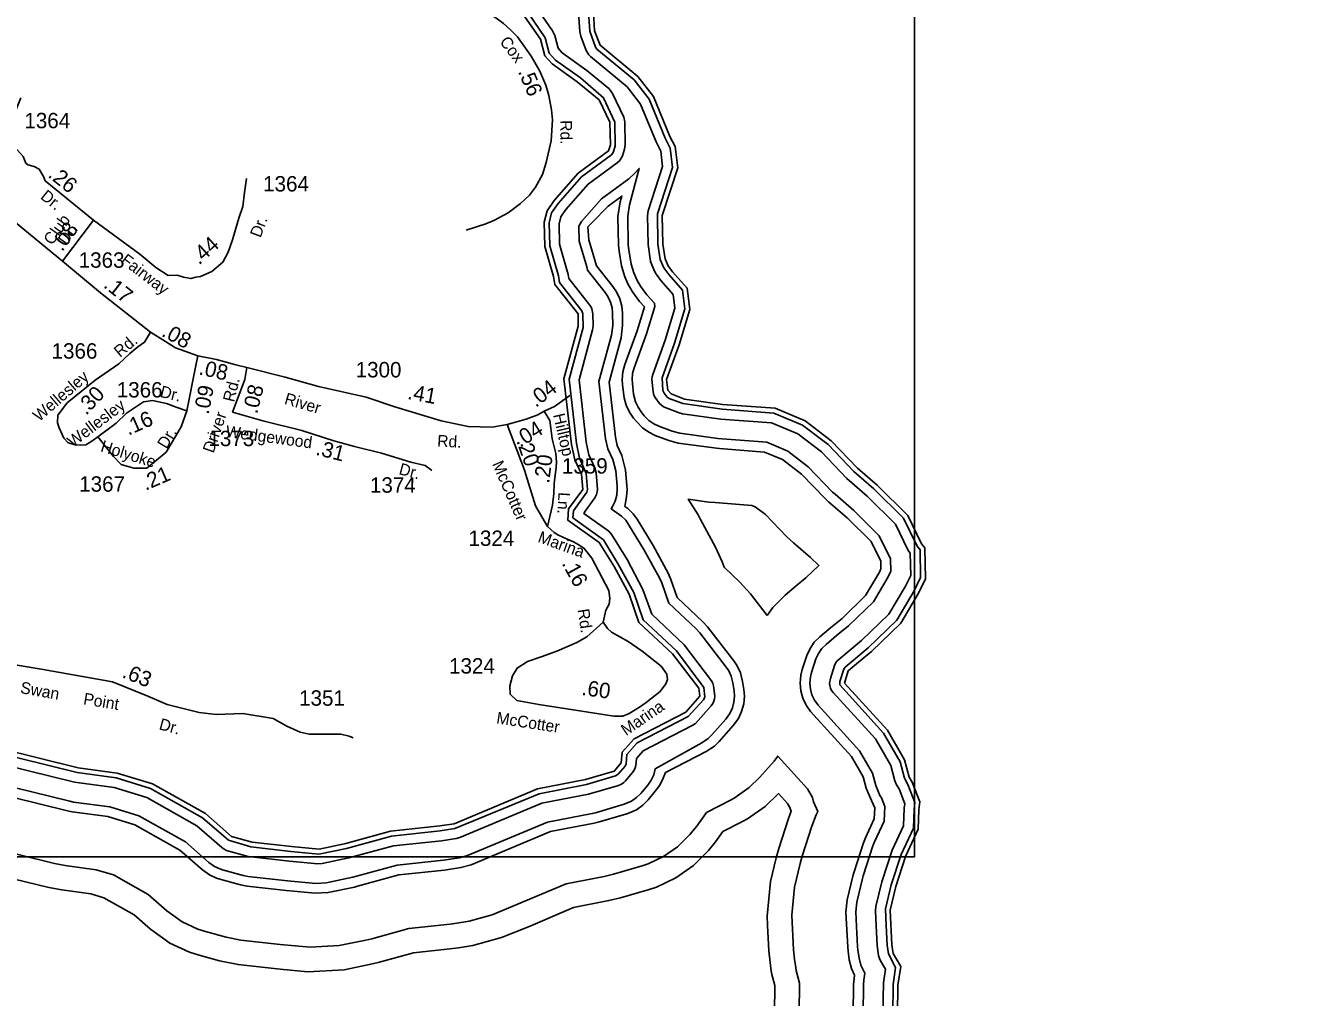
# Model space of a CAD drawing. Extents: x 2532689 to 2764727, y 536648 to 732970.
# Drawn here: x 2602829 to 2613131, y 635210 to 643101 of the extents above; entities that cross this region are included whole.
import ezdxf

# ---------------------------------------------------------------- set-up
doc = ezdxf.new("R2010")
doc.units = 0
for name, color, linetype in [('Exist Hydrographic Buffer Line', 7, 'Continuous'), ('Exist Hydrographic River Shore', 7, 'Continuous'), ('Exist Road Secondary Mileage Hundredths English Label', 7, 'Continuous'), ('Exist Road Secondary Type 51 Attributed', 7, 'Continuous'), ('Exist Road Secondary Type 51 Label', 7, 'Continuous'), ('Exist Road Secondary Type 51 Number Label', 7, 'Continuous'), ('Map Preparation Inset Cut Line', 7, 'Continuous')]:
    doc.layers.add(name, color=color, linetype=linetype)

msp = doc.modelspace()

# ---------------------------------------------------------------- linework, layer by layer
at = {"layer": 'Exist Hydrographic Buffer Line'}
for points in [[(2606910, 643202), (2607049, 642999)], [(2607643, 636932), (2607669, 636943), (2607687, 636955), (2607701, 636970), (2607758, 637038), (2607770, 637055), (2607779, 637074), (2607785, 637094), (2607789, 637151), (2607845, 637213), (2608246, 637420), (2608268, 637435), (2608395, 637577), (2608409, 637596), (2608418, 637615), (2608423, 637636), (2608425, 637656), (2608414, 637740), (2608408, 637763), (2608399, 637782), (2608176, 638072), (2607913, 638321), (2607842, 638523), (2607713, 638766), (2607590, 638967), (2607565, 638996), (2607361, 639140), (2607374, 639158), (2607451, 639265), (2607466, 639294), (2607471, 639314), (2607473, 639335), (2607462, 639470), (2607451, 639509), (2607404, 639614), (2607381, 639719), (2607323, 640223), (2607433, 640629), (2607437, 640663), (2607435, 640761), (2607428, 640800), (2607419, 640819), (2607241, 641046), (2607236, 641079), (2607165, 641324), (2607161, 641489), (2607175, 641546), (2607216, 641606), (2607398, 641812), (2607633, 641985), (2607654, 642005), (2607666, 642022), (2607675, 642041), (2607692, 642095), (2607698, 642134), (2607694, 642318), (2607687, 642356), (2607595, 642548), (2607579, 642573), (2607564, 642588), (2607386, 642735), (2607187, 642879), (2607154, 642915), (2607126, 643020), (2607109, 643057), (2607000, 643213)], [(2607320, 643206), (2607330, 643048), (2607338, 643013), (2607382, 642897), (2607402, 642862), (2607417, 642847), (2607714, 642601), (2607823, 642462), (2607949, 642155), (2607987, 642081), (2608002, 641956), (2607884, 641595), (2607878, 641555), (2607883, 641322), (2607904, 641188), (2607913, 641158), (2607939, 641100), (2607951, 641079), (2607986, 641031), (2608088, 640917), (2608101, 640806), (2608023, 640547), (2607921, 640267), (2607916, 640247), (2607914, 640226), (2607925, 640127)], [(2609958, 639100), (2609717, 639340), (2609555, 639480), (2609344, 639699), (2609138, 639856), (2608905, 639953), (2608484, 639985), (2608165, 640031), (2608056, 640072), (2608039, 640084), (2608013, 640116), (2608004, 640137), (2607997, 640240), (2608099, 640522), (2608182, 640799), (2608164, 640951), (2608051, 641078), (2608012, 641133), (2607983, 641201), (2607963, 641324), (2607960, 641570), (2608083, 641948), (2608064, 642105), (2608023, 642185), (2607893, 642503), (2607771, 642658), (2607468, 642909), (2607457, 642925), (2607410, 643053), (2607400, 643208)], [(2607049, 642999), (2607082, 642875), (2607133, 642819), (2607335, 642674), (2607523, 642513), (2607614, 642316), (2607616, 642120), (2607600, 642068), (2607586, 642050), (2607343, 641871), (2607153, 641655), (2607101, 641579), (2607081, 641498), (2607085, 641312), (2607157, 641068), (2607164, 641013), (2607346, 640783), (2607355, 640759), (2607356, 640650), (2607242, 640229), (2607302, 639706), (2607327, 639588), (2607382, 639463), (2607393, 639335), (2607386, 639312), (2607278, 639162), (2607274, 639104), (2607521, 638925), (2607642, 638728), (2607767, 638497), (2607844, 638276), (2608113, 638023), (2608335, 637728), (2608345, 637650), (2608335, 637630), (2608209, 637492), (2607795, 637278), (2607711, 637184), (2607706, 637108), (2607697, 637089), (2607640, 637022), (2607620, 637009), (2607385, 636939), (2606999, 636865), (2606315, 636581), (2606197, 636563), (2605802, 636521), (2605437, 636421), (2605210, 636375), (2604984, 636396), (2604660, 636433), (2604477, 636488), (2604268, 636670), (2603845, 636908), (2603567, 636993), (2603249, 637036), (2602294, 637271)], [(2609575, 635788), (2609570, 635906), (2609577, 635985), (2609623, 636177), (2609629, 636199), (2609708, 636442), (2609721, 636473), (2609799, 636642), (2609804, 636762), (2609777, 636832), (2609765, 636851), (2609731, 636930), (2609705, 637032), (2609600, 637214), (2609263, 637583), (2609235, 637623), (2609214, 637667), (2609201, 637714), (2609197, 637763), (2609201, 637812), (2609211, 637849), (2609246, 637959), (2609267, 638003), (2609295, 638043), (2609329, 638077), (2609414, 638149), (2609511, 638228), (2609712, 638423), (2609832, 638625), (2609854, 638671), (2609852, 638770), (2609760, 638958), (2609554, 639164), (2609401, 639295), (2609381, 639313), (2609183, 639519), (2609017, 639646), (2608848, 639717), (2608451, 639747), (2608140, 639791), (2608079, 639806), (2607971, 639848), (2607930, 639867), (2607890, 639895), (2607853, 639932), (2607827, 639964), (2607802, 640001), (2607781, 640045), (2607766, 640108), (2607756, 640193), (2607754, 640226), (2607758, 640275), (2607771, 640322), (2607871, 640598), (2607938, 640820), (2607935, 640847), (2607874, 640915), (2607857, 640936), (2607822, 640984), (2607793, 641035), (2607767, 641093), (2607746, 641163), (2607727, 641280), (2607723, 641319), (2607718, 641552), (2607732, 641645), (2607812, 641940), (2607777, 641902), (2607728, 641856), (2607506, 641693), (2607343, 641508), (2607322, 641471), (2607324, 641349), (2607386, 641142), (2607392, 641113), (2607535, 640932), (2607558, 640899), (2607578, 640854), (2607591, 640807), (2607595, 640764), (2607597, 640666), (2607587, 640587)], [(2609549, 635076), (2609552, 635316), (2609556, 635363), (2609560, 635392), (2609535, 635446), (2609517, 635517), (2609507, 635586), (2609504, 635620), (2609490, 635902), (2609499, 636003), (2609545, 636196), (2609553, 636223), (2609632, 636466), (2609648, 636507), (2609720, 636661), (2609723, 636749), (2609697, 636809), (2609654, 636910), (2609630, 637002), (2609535, 637166), (2609201, 637532), (2609166, 637583), (2609139, 637640), (2609123, 637701), (2609117, 637763), (2609123, 637826), (2609135, 637873), (2609171, 637986), (2609198, 638043), (2609233, 638094), (2609278, 638138), (2609364, 638211), (2609458, 638288), (2609649, 638473), (2609761, 638663), (2609774, 638689), (2609772, 638751), (2609694, 638911), (2609500, 639105), (2609349, 639234), (2609324, 639258), (2609130, 639459), (2608976, 639576), (2608829, 639638), (2608462, 639666), (2608439, 639668), (2608129, 639711), (2608051, 639731), (2607942, 639773), (2607890, 639798), (2607839, 639834), (2607791, 639882), (2607765, 639913), (2607732, 639961), (2607706, 640018), (2607690, 640079), (2607687, 640099), (2607677, 640184), (2607674, 640226), (2607680, 640289), (2607696, 640349), (2607795, 640623), (2607854, 640817), (2607815, 640861), (2607793, 640889), (2607758, 640937), (2607720, 641002), (2607694, 641060), (2607667, 641150), (2607648, 641267), (2607643, 641317), (2607638, 641550), (2607656, 641669), (2607671, 641715), (2607561, 641634), (2607426, 641497), (2607394, 641465), (2607404, 641361), (2607466, 641148), (2607597, 640982)], [(2607597, 640982), (2607627, 640939), (2607653, 640882), (2607670, 640821), (2607675, 640766), (2607677, 640667), (2607665, 640566), (2607567, 640204), (2607618, 639758), (2607633, 639690), (2607670, 639609), (2607701, 639491), (2607712, 639367), (2607713, 639335), (2607708, 639273), (2607695, 639197), (2607719, 639180), (2607763, 639135), (2607794, 639092), (2607924, 638880), (2608046, 638655), (2608069, 638602), (2608120, 638456), (2608328, 638261), (2608366, 638219), (2608580, 637942), (2608607, 637902), (2608633, 637845), (2608651, 637776), (2608661, 637711), (2608665, 637656), (2608660, 637594), (2608643, 637533), (2608617, 637476), (2608575, 637418), (2608461, 637289), (2608423, 637251), (2608356, 637207), (2608025, 637036), (2608005, 636992), (2607978, 636935), (2607942, 636884), (2607885, 636816), (2607841, 636771), (2607789, 636735), (2607732, 636709), (2607711, 636702), (2607479, 636633), (2607445, 636625), (2607092, 636557), (2606448, 636288), (2606364, 636265), (2606231, 636245), (2605861, 636205), (2605524, 636113), (2605502, 636107), (2605286, 636063), (2605181, 636057), (2604947, 636078), (2604629, 636114), (2604575, 636125), (2604408, 636171), (2604380, 636179), (2604323, 636206), (2604266, 636247), (2604082, 636407), (2603719, 636612), (2603498, 636679), (2603210, 636718), (2603172, 636725), (2602282, 636944)], [(2607587, 640587), (2607485, 640210), (2607539, 639745), (2607557, 639665), (2607597, 639576), (2607621, 639484), (2607632, 639360), (2607633, 639335), (2607629, 639287), (2607616, 639239), (2607596, 639195), (2607585, 639178), (2607649, 639132), (2607667, 639118), (2607702, 639084), (2607726, 639050), (2607853, 638842), (2607975, 638617), (2607994, 638576), (2608051, 638411), (2608273, 638203), (2608303, 638170), (2608517, 637893), (2608538, 637862), (2608558, 637818), (2608572, 637764), (2608582, 637699), (2608585, 637656), (2608581, 637608), (2608568, 637561), (2608548, 637516), (2608515, 637471), (2608401, 637342), (2608371, 637313), (2608320, 637278), (2607942, 637067), (2607929, 637019), (2607909, 636975), (2607881, 636935), (2607824, 636867), (2607789, 636833), (2607749, 636805), (2607689, 636779), (2607456, 636710), (2607430, 636704), (2607068, 636634), (2606417, 636362), (2606352, 636344), (2606223, 636324), (2605846, 636284), (2605486, 636186), (2605270, 636141), (2605188, 636136), (2604956, 636157), (2604638, 636194), (2604596, 636202), (2604429, 636248), (2604407, 636255), (2604363, 636275), (2604319, 636307), (2604129, 636473), (2603750, 636686), (2603515, 636757), (2603220, 636797), (2603191, 636803), (2602285, 637026)], [(2607925, 640127), (2607931, 640100), (2607940, 640081), (2607977, 640033), (2607993, 640017), (2608010, 640005), (2608136, 639956), (2608163, 639949), (2608473, 639906), (2608886, 639874), (2609098, 639786), (2609290, 639639), (2609497, 639424), (2609663, 639281), (2609892, 639053), (2609996, 638839), (2610011, 638816), (2610015, 638637), (2609973, 638550), (2609839, 638323), (2609617, 638108), (2609516, 638025), (2609432, 637955), (2609417, 637940), (2609405, 637923), (2609396, 637904), (2609363, 637800), (2609357, 637763), (2609359, 637742), (2609364, 637722), (2609373, 637703), (2609385, 637686), (2609730, 637309), (2609854, 637093), (2609886, 636970), (2609900, 636936), (2609921, 636904), (2609967, 636783), (2609963, 636746), (2609958, 636604), (2609866, 636406), (2609781, 636149), (2609733, 635948), (2609729, 635914), (2609736, 635791)], [(2608850, 638312), (2608714, 638488), (2608628, 638582), (2608500, 638703), (2608485, 638747), (2608432, 638865), (2608310, 639090), (2608289, 639127), (2608210, 639256), (2608378, 639232), (2608429, 639227), (2608726, 639205), (2608754, 639192), (2608836, 639130), (2609007, 638952), (2609063, 638900), (2609201, 638782), (2609270, 638718), (2609165, 638617), (2609086, 638552), (2608995, 638475), (2608897, 638377), (2608850, 638312)], [(2609816, 635795), (2609810, 635929), (2609857, 636124), (2609938, 636372), (2610038, 636585), (2610043, 636738), (2610049, 636794), (2609992, 636940), (2609964, 636990), (2609929, 637124), (2609795, 637356), (2609440, 637749), (2609439, 637775), (2609472, 637876), (2609484, 637893), (2609566, 637963), (2609671, 638048), (2609903, 638273), (2610044, 638512), (2610095, 638619), (2610091, 638845), (2610068, 638874), (2609958, 639100)], [(2602291, 637189), (2603229, 636958), (2603549, 636914), (2603814, 636834), (2604222, 636604), (2604424, 636427), (2604443, 636414), (2604462, 636405), (2604638, 636356), (2604974, 636316), (2605202, 636296), (2605238, 636298), (2605454, 636343), (2605816, 636442), (2606206, 636483), (2606327, 636502), (2606356, 636510), (2607022, 636788), (2607400, 636861), (2607643, 636932)], [(2602266, 636495), (2603067, 636298), (2603151, 636282), (2603404, 636248), (2603545, 636205), (2603827, 636046), (2603977, 635915), (2604103, 635825), (2604230, 635766), (2604291, 635746), (2604458, 635700), (2604579, 635677), (2604897, 635641), (2605141, 635618), (2605376, 635632), (2605592, 635677), (2605641, 635688), (2605943, 635771), (2606278, 635807), (2606315, 635812), (2606431, 635830), (2606618, 635882), (2607219, 636134), (2607528, 636193), (2607603, 636211), (2607835, 636280), (2607883, 636295), (2608009, 636354), (2608123, 636434), (2608222, 636533), (2608279, 636601), (2608357, 636712), (2608558, 636816), (2608591, 636834), (2608705, 636914), (2608792, 636998), (2608906, 637128), (2608936, 637170), (2609178, 636905), (2609219, 636834), (2609227, 636800), (2609262, 636720), (2609249, 636693), (2609214, 636602), (2609135, 636359), (2609117, 636298)], [(2606914, 635784), (2607277, 635941), (2607566, 635997), (2607660, 636020), (2607892, 636088), (2607951, 636107), (2608109, 636181), (2608252, 636281), (2608375, 636404), (2608432, 636473), (2608491, 636557), (2608650, 636638), (2608691, 636661), (2608834, 636761), (2608942, 636866), (2609016, 636786), (2609032, 636757), (2609046, 636723), (2609023, 636664), (2608944, 636421), (2608923, 636345), (2608877, 636152), (2608851, 635870), (2608854, 635795)], [(2602249, 636289), (2603019, 636104), (2603124, 636084), (2603361, 636052), (2603466, 636020), (2603711, 635882), (2603845, 635764), (2604003, 635652), (2604161, 635578), (2604239, 635553), (2604406, 635508), (2604556, 635478), (2604874, 635442), (2604898, 635440), (2605123, 635419), (2605417, 635436), (2605633, 635481), (2605694, 635496), (2605980, 635574), (2606299, 635608), (2606345, 635614), (2606461, 635632), (2606695, 635698), (2606914, 635784)], [(2609117, 636298), (2609071, 636106), (2609050, 635880), (2609064, 635598), (2609072, 635522)], [(2608854, 635795), (2608865, 635588), (2608874, 635494), (2608884, 635425), (2608889, 635396), (2608912, 635307), (2608909, 635084)], [(2610230, 634303), (2610191, 634327), (2610030, 634442), (2609993, 634473), (2609865, 634602), (2609848, 634621), (2609746, 634745), (2609698, 634829), (2609646, 634978), (2609633, 635023), (2609629, 635075), (2609632, 635315), (2609635, 635352), (2609643, 635408), (2609631, 635430), (2609610, 635474), (2609596, 635529), (2609586, 635597), (2609583, 635624), (2609575, 635788)], [(2609736, 635791), (2609744, 635632), (2609754, 635552), (2609761, 635528), (2609769, 635509), (2609810, 635440), (2609794, 635329), (2609789, 635073), (2609791, 635051), (2609796, 635032), (2609849, 634883), (2609869, 634847), (2609972, 634723), (2610107, 634585), (2610123, 634572), (2610283, 634457), (2610898, 634153), (2611106, 634079), (2611738, 633775), (2611965, 633604), (2612368, 633384), (2612394, 633373), (2613157, 633165), (2613188, 633160)], [(2613599, 633293), (2613575, 633282), (2613178, 633242), (2612406, 633454), (2612013, 633668), (2611780, 633843), (2611137, 634153), (2610934, 634224), (2610330, 634522), (2610164, 634641), (2610033, 634774), (2609925, 634909), (2609869, 635072), (2609873, 635317), (2609893, 635455), (2609834, 635564), (2609823, 635636), (2609816, 635795)], [(2609109, 635082), (2609113, 635328), (2609086, 635430), (2609082, 635454), (2609072, 635522)]]:
    msp.add_lwpolyline(points, dxfattribs=at)
at = {"layer": 'Exist Hydrographic River Shore'}
for points in [[(2608305, 637656), (2608295, 637722), (2608081, 637999), (2607809, 638254), (2607729, 638484), (2607607, 638708), (2607487, 638904), (2607233, 639084), (2607239, 639176), (2607353, 639335), (2607342, 639459), (2607289, 639575), (2607262, 639699), (2607201, 640232), (2607317, 640660), (2607315, 640759), (2607126, 640997), (2607117, 641062), (2607045, 641306), (2607041, 641503), (2607064, 641595), (2607121, 641680), (2607316, 641901), (2607562, 642082), (2607578, 642132), (2607574, 642315), (2607487, 642496), (2607309, 642643), (2607106, 642789), (2607046, 642855), (2607010, 642989), (2606865, 643197)], [(2609477, 637763), (2609509, 637863), (2609591, 637932), (2609697, 638018), (2609934, 638248), (2610079, 638493), (2610135, 638610), (2610130, 638860), (2610104, 638892), (2609991, 639123), (2609744, 639369), (2609583, 639507), (2609370, 639729), (2609158, 639891), (2608914, 639993), (2608489, 640025), (2608179, 640068), (2608070, 640109), (2608044, 640141), (2608034, 640226), (2608137, 640509), (2608223, 640795), (2608202, 640968), (2608083, 641101), (2608048, 641149), (2608022, 641207), (2608003, 641325), (2607998, 641558), (2608124, 641944), (2608103, 642117), (2608060, 642200), (2607928, 642523), (2607800, 642686), (2607494, 642939), (2607450, 643056), (2607440, 643209)], [(2609909, 635072), (2609912, 635312), (2609934, 635463), (2609873, 635569), (2609863, 635638), (2609849, 635920), (2609895, 636112), (2609974, 636355), (2610077, 636576), (2610082, 636734), (2610089, 636800), (2610028, 636958), (2610002, 637000), (2609966, 637139), (2609827, 637380), (2609477, 637763)], [(2608305, 637656), (2608191, 637527), (2607770, 637310), (2607672, 637201), (2607666, 637115), (2607609, 637047), (2607377, 636979), (2606987, 636904), (2606309, 636620), (2606193, 636603), (2605794, 636560), (2605429, 636460), (2605213, 636415), (2604988, 636436), (2604670, 636472), (2604503, 636518), (2604291, 636703), (2603861, 636945), (2603575, 637032), (2603258, 637075), (2602295, 637312)]]:
    msp.add_lwpolyline(points, dxfattribs=at)
at = {"layer": 'Exist Road Secondary Type 51 Attributed'}
msp.add_line((2603130, 641186), (2603381, 641520), dxfattribs=at)
for points in [[(2606417, 643273), (2606569, 643213), (2606591, 643195), (2606649, 643161), (2606711, 643116), (2606766, 643066), (2606824, 643007), (2606935, 642851), (2607004, 642729), (2607055, 642617), (2607079, 642533), (2607101, 642416), (2607109, 642333), (2607097, 642165), (2607057, 641988), (2607026, 641891), (2606970, 641788), (2606921, 641723), (2606848, 641655), (2606749, 641579), (2606638, 641521), (2606567, 641491), (2606407, 641440)], [(2602792, 642514), (2602754, 642417), (2602718, 642304), (2602712, 642229), (2602721, 642171), (2602741, 642116), (2602812, 642038), (2602832, 641983), (2602848, 641970), (2602901, 641956), (2602942, 641934), (2602969, 641889), (2602977, 641874), (2602990, 641840), (2603381, 641520)], [(2603381, 641520), (2603759, 641243), (2603889, 641135), (2603988, 641070), (2604060, 641074), (2604112, 641057), (2604171, 641046), (2604214, 641058), (2604250, 641062), (2604342, 641103), (2604431, 641180), (2604474, 641260), (2604510, 641359), (2604536, 641445), (2604563, 641537), (2604594, 641631), (2604608, 641745), (2604624, 641858)], [(2602442, 641746), (2602470, 641729), (2603130, 641186)], [(2603130, 641186), (2603439, 640931), (2603844, 640611)], [(2603417, 639762), (2603360, 639722), (2603319, 639697), (2603278, 639694), (2603234, 639697), (2603177, 639713), (2603142, 639750), (2603103, 639834), (2603090, 639876), (2603092, 639938), (2603169, 640037), (2603396, 640220), (2603589, 640354), (2603678, 640437), (2603741, 640491), (2603797, 640530), (2603844, 640611)], [(2603844, 640611), (2603966, 640536), (2604049, 640483), (2604123, 640457), (2604230, 640419)], [(2604230, 640419), (2604213, 640339), (2604141, 639971)], [(2604230, 640419), (2604380, 640390), (2604538, 640346), (2604626, 640323)], [(2604626, 640323), (2604610, 640227), (2604511, 639962)], [(2604626, 640323), (2604939, 640246), (2605209, 640170), (2605596, 640083), (2605828, 640004), (2606203, 639890), (2606423, 639844), (2606619, 639840), (2606741, 639861)], [(2607040, 639969), (2607124, 640007), (2607249, 640098)], [(2604141, 639971), (2604053, 640001), (2603974, 640031), (2603861, 640056), (2603787, 640045), (2603649, 639953), (2603565, 639873), (2603417, 639762)], [(2604141, 639971), (2604094, 639842), (2603972, 639636), (2603815, 639507)], [(2606741, 639861), (2606894, 639905), (2606990, 639940), (2607040, 639969)], [(2607040, 639969), (2607086, 639893), (2607094, 639831), (2607106, 639745), (2607134, 639627), (2607141, 639557), (2607137, 639514), (2607120, 639382), (2607118, 639301), (2607108, 639206), (2607066, 639033)], [(2604511, 639962), (2604757, 639890), (2605074, 639813), (2605334, 639729), (2605502, 639683), (2605721, 639629), (2605958, 639557), (2606075, 639528), (2606115, 639499), (2606128, 639487)], [(2603815, 639507), (2603709, 639506), (2603606, 639538), (2603545, 639601), (2603417, 639762)], [(2606741, 639861), (2606880, 639490), (2606970, 639201), (2607020, 639111), (2607066, 639033)], [(2607066, 639033), (2607120, 638986), (2607150, 638965), (2607197, 638945), (2607278, 638910), (2607322, 638885), (2607366, 638855), (2607426, 638776), (2607564, 638514), (2607573, 638451), (2607568, 638403), (2607541, 638354), (2607518, 638256)], [(2607518, 638256), (2607387, 638139), (2607304, 638093), (2607142, 638021), (2607017, 637976), (2606905, 637939), (2606822, 637885), (2606782, 637821), (2606761, 637739), (2606763, 637672), (2606819, 637621), (2606998, 637589), (2607312, 637541)], [(2607312, 637541), (2607606, 637493), (2607680, 637493), (2607731, 637517), (2607814, 637568), (2607867, 637605), (2607981, 637693), (2608029, 637757), (2608040, 637792), (2608037, 637835), (2607989, 637899), (2607835, 638021), (2607723, 638101), (2607654, 638139), (2607587, 638176), (2607555, 638205), (2607518, 638256)], [(2602282, 638084), (2602357, 638006), (2602465, 637956), (2602974, 637874), (2603536, 637774), (2603824, 637656), (2603981, 637588), (2604239, 637524), (2604378, 637508), (2604595, 637517), (2604841, 637476), (2604951, 637412), (2605060, 637364), (2605134, 637348), (2605390, 637347), (2605458, 637333), (2605489, 637317)]]:
    msp.add_lwpolyline(points, dxfattribs=at)
at = {"layer": 'Map Preparation Inset Cut Line'}
msp.add_lwpolyline([(2549571, 680600), (2610045, 680600), (2610045, 636352), (2549571, 636352)], close=True, dxfattribs=at)

# ---------------------------------------------------------------- texts
at = {"layer": 'Exist Road Secondary Mileage Hundredths English Label'}
for s, rotation, p in [('.56', 292.9001, (2606826, 642727)), ('.26', 321.3568, (2603005, 641876)), ('.08', 54.2096, (2603128, 641259)), ('.44', 41.7837, (2604239, 641152)), ('.17', 321.6431, (2603456, 640980)), ('.08', 331.4255, (2603927, 640583)), ('.08', 347.1306, (2604231, 640269)), ('.09', 78.8407, (2604316, 639938)), ('.08', 76.072, (2604710, 639942)), ('.41', 349.5129, (2605925, 640069)), ('.04', 37.6695, (2606972, 639995)), ('.30', 46.8672, (2603323, 639931)), ('.16', 23.585, (2603665, 639770)), ('.04', 31.4891, (2606845, 639671)), ('.31', 345.8782, (2605179, 639617)), ('.20', 289.1673, (2606813, 639729)), ('.20', 82.5416, (2607080, 639379)), ('.21', 23.2952, (2603805, 639323)), ('.16', 298.9084, (2607180, 638734)), ('.63', 337.9097, (2603607, 637812)), ('.60', 351.9565, (2607339, 637667))]:
    msp.add_text(s, height=125, rotation=rotation, dxfattribs=at).set_placement(p)
at = {"layer": 'Exist Road Secondary Type 51 Label'}
for s, rotation, p in [('Cox', 307.378, (2606674, 642967)), ('Rd.', 270.5541, (2607171, 642331)), ('Dr.', 321.4168, (2602945, 641700)), ('Club', 54.2696, (2603046, 641311)), ('Dr.', 69.5004, (2604738, 641372)), ('Dr.', 54.2696, (2603163, 641311)), ('Fairway', 322.5399, (2603596, 641179)), ('Rd.', 40.4106, (2603598, 640401)), ('Wellesley', 40.7372, (2602941, 639880)), ('Dr.', 345.8698, (2603916, 640087)), ('Rd.', 76.132, (2604523, 640038)), ('River', 343.7003, (2604925, 640030)), ('Wellesley', 36.9668, (2603215, 639672)), ('Driver', 71.2903, (2604356, 639624)), ('Hilltop', 283.0826, (2607112, 639940)), ('Dr.', 58.8796, (2603975, 639657)), ('Wedgewood', 352.3406, (2604451, 639761)), ('Rd.', 356.8114, (2606170, 639683)), ('Holyoke', 342.7203, (2603433, 639645)), ('McCotter', 293.6536, (2606616, 639542)), ('Dr.', 345.2, (2605855, 639459)), ('Ln.', 266.6541, (2607157, 639314)), ('Marina', 340.1636, (2606982, 638910)), ('Rd.', 278.4623, (2607311, 638359)), ('Swan', 349.9549, (2602783, 637682)), ('Point', 350.5683, (2603295, 637591)), ('Marina', 34.5116, (2607705, 637331)), ('McCotter', 351.311, (2606648, 637436)), ('Dr.', 344.7412, (2603908, 637388))]:
    msp.add_text(s, height=95, rotation=rotation, dxfattribs=at).set_placement(p)
at = {"layer": 'Exist Road Secondary Type 51 Number Label'}
for s, p in [('1364', (2602821, 642266)), ('1364', (2604759, 641753)), ('1363', (2603262, 641134)), ('1366', (2603042, 640396)), ('1300', (2605510, 640244)), ('1366', (2603571, 640081)), ('1373', (2604315, 639686)), ('1359', (2607184, 639463)), ('1367', (2603266, 639316)), ('1374', (2605626, 639308)), ('1324', (2606426, 638876)), ('1324', (2606268, 637840)), ('1351', (2605051, 637579))]:
    msp.add_text(s, height=125, rotation=359.94, dxfattribs=at).set_placement(p)

doc.saveas('drawing.dxf')
